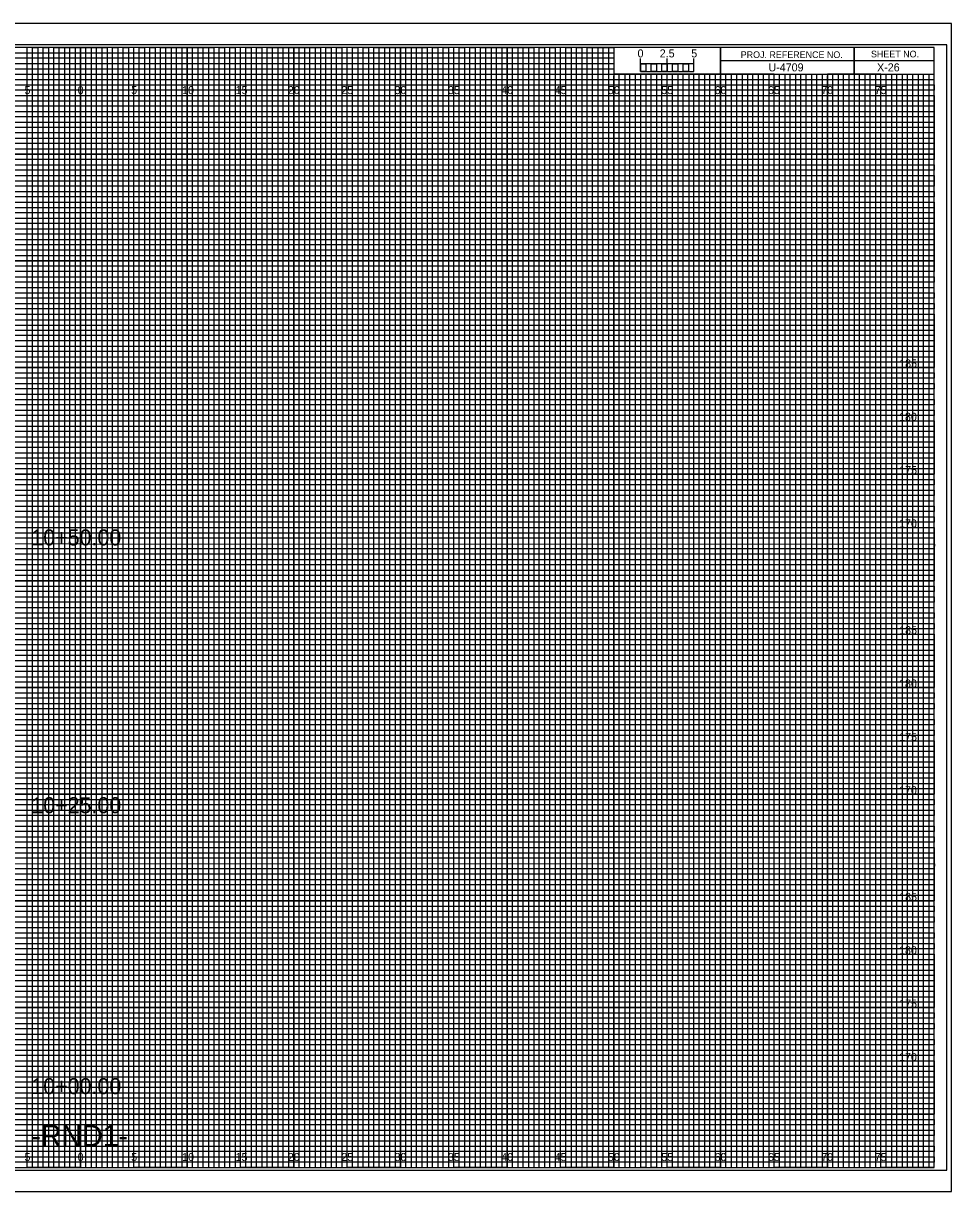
# Model space of a CAD drawing. Extents: x -7 to 162, y -2 to 107.
# Drawn here: x 74.6 to 161.7, y -2.3 to 107.3 of the extents above; entities that cross this region are included whole.
import ezdxf

# ---------------------------------------------------------------- set-up
doc = ezdxf.new("R2010")
doc.units = 0
for name, color, linetype in [('Prop XS Alignment Label', 7, 'Continuous'), ('Prop XS Bar Scale Labels', 7, 'Continuous'), ('Prop XS Elevation Labels', 7, 'Continuous'), ('Prop XS Offset Labels', 7, 'Continuous'), ('Prop XS Project Number', 7, 'Continuous'), ('Prop XS Sheet Number', 7, 'Continuous'), ('Prop XS Station Labels', 7, 'Continuous'), ('Sheet Cross Section CELL', 7, 'Continuous'), ('Sheet Cross Section Grid Major CELL', 7, 'Continuous'), ('Sheet Cross Section Grid Middle CELL', 7, 'Continuous'), ('Sheet Cross Section Grid Minor 1 CELL', 7, 'Continuous'), ('Sheet Cross Section Grid Minor 2 CELL', 7, 'Continuous'), ('Sheet Cross Section Scale CELL', 7, 'Continuous'), ('Sheet Cutting Line CELL', 7, 'Continuous'), ('Sheet DOT Grid CELL', 7, 'Continuous'), ('Sheet Plot Border Inside CELL', 7, 'Continuous'), ('Sheet Plot Border Outside CELL', 7, 'Continuous')]:
    doc.layers.add(name, color=color, linetype=linetype)

msp = doc.modelspace()

# ---------------------------------------------------------------- linework, layer by layer
at = {"layer": 'Sheet Cross Section CELL'}
for p, q in [((152.5, 105), (152.5, 102.5)), ((152.5, 102.5), (152.5, 105)), ((160, 103.75), (140, 103.75)), ((140, 103.75), (140, 102.5)), ((140, 102.5), (160, 102.5))]:
    msp.add_line(p, q, dxfattribs=at)
for points in [[(160, 105), (0, 105), (0, 0), (160, 0)], [(140, 105), (130, 105), (130, 102.52), (140, 102.52)], [(160, 105), (140, 105), (140, 102.5), (160, 102.5)]]:
    msp.add_lwpolyline(points, close=True, dxfattribs=at)
at = {"layer": 'Sheet Cross Section Grid Major CELL'}
for p, q in [((75, 105), (70, 105)), ((75, 0), (75, 105)), ((85, 105), (80, 105)), ((80, 105), (80, 0)), ((85, 0), (85, 105)), ((95, 105), (90, 105)), ((90, 105), (90, 0)), ((95, 0), (95, 105)), ((105, 105), (100, 105)), ((100, 105), (100, 0)), ((105, 0), (105, 105)), ((115, 105), (110, 105)), ((110, 105), (110, 0)), ((115, 0), (115, 105)), ((125, 105), (120, 105)), ((120, 105), (120, 0)), ((125, 0), (125, 105)), ((130, 105), (130, 0)), ((135, 0), (135, 102.5)), ((145, 102.5), (140, 102.5)), ((140, 102.5), (140, 0)), ((145, 0), (145, 102.5)), ((155, 102.5), (150, 102.5)), ((150, 102.5), (150, 0)), ((155, 0), (155, 102.5)), ((80, 0), (75, 0)), ((90, 0), (85, 0)), ((100, 0), (95, 0)), ((110, 0), (105, 0)), ((120, 0), (115, 0)), ((130, 0), (125, 0)), ((140, 0), (135, 0)), ((150, 0), (145, 0)), ((160, 0), (155, 0)), ((160, 0), (160, 0))]:
    msp.add_line(p, q, dxfattribs=at)
for points in [[(0, 100), (160, 100), (160, 95), (0, 95)], [(0, 90), (160, 90), (160, 85), (0, 85)], [(0, 80), (160, 80), (160, 75), (0, 75)], [(0, 70), (160, 70), (160, 65), (0, 65)], [(0, 60), (160, 60), (160, 55), (0, 55)], [(0, 50), (160, 50), (160, 45), (0, 45)], [(0, 40), (160, 40), (160, 35), (0, 35)], [(0, 30), (160, 30), (160, 25), (0, 25)], [(0, 20), (160, 20), (160, 15), (0, 15)], [(0, 10), (160, 10), (160, 5), (0, 5)]]:
    msp.add_lwpolyline(points, dxfattribs=at)
at = {"layer": 'Sheet Cross Section Grid Middle CELL'}
for points in [[(72.5, 0), (77.5, 0), (77.5, 105), (82.5, 105), (82.5, 0), (87.5, 0), (87.5, 105), (92.5, 105), (92.5, 0), (97.5, 0), (97.5, 105), (102.5, 105), (102.5, 0), (107.5, 0), (107.5, 105), (112.5, 105), (112.5, 0), (117.5, 0), (117.5, 105), (122.5, 105), (122.5, 0), (127.5, 0), (127.5, 105), (129.97, 105), (130, 105), (130, 102.5), (132.5, 102.5), (132.5, 0), (137.5, 0), (137.5, 102.5), (142.5, 102.5), (142.5, 0), (147.5, 0), (147.5, 102.5), (152.5, 102.5), (152.5, 0), (157.5, 0), (157.5, 102.5)], [(0, 102.5), (137.5, 102.5)], [(0, 92.5), (160, 92.5), (160, 97.5), (0, 97.5)], [(0, 82.5), (160, 82.5), (160, 87.5), (0, 87.5)], [(0, 72.5), (160, 72.5), (160, 77.5), (0, 77.5)], [(0, 62.5), (160, 62.5), (160, 67.5), (0, 67.5)], [(0, 52.5), (160, 52.5), (160, 57.5), (0, 57.5)], [(0, 42.5), (160, 42.5), (160, 47.5), (0, 47.5)], [(0, 32.5), (160, 32.5), (160, 37.5), (0, 37.5)], [(0, 22.5), (160, 22.5), (160, 27.5), (0, 27.5)], [(0, 12.5), (160, 12.5), (160, 17.5), (0, 17.5)], [(0, 2.5), (160, 2.5), (160, 7.5), (0, 7.5)]]:
    msp.add_lwpolyline(points, dxfattribs=at)
at = {"layer": 'Sheet Cross Section Grid Minor 1 CELL'}
for p, q in [((0, 104.5), (130, 104.5)), ((130, 104.5), (130, 103.99)), ((130, 103.99), (0, 103.99)), ((0, 103.5), (130, 103.5)), ((130, 102.95), (0, 102.95)), ((130, 103.5), (130, 102.95)), ((0, 102), (160, 102))]:
    msp.add_line(p, q, dxfattribs=at)
for points in [[(0, 101.5), (135, 101.5), (160, 101.5), (160, 101), (0, 101)], [(0, 100.5), (160, 100.5), (160, 99.5), (0, 99.5)], [(0, 99), (160, 99), (160, 98.5), (0, 98.49)], [(0, 98), (160, 98), (160, 97), (0, 97)], [(0, 96.5), (160, 96.5), (160, 96), (0, 96)], [(0, 95.5), (160, 95.5), (160, 94.5), (0, 94.5)], [(0, 94), (160, 94), (160, 93.5), (0, 93.5)], [(0, 93), (160, 93), (160, 92), (0, 92)], [(0, 91.5), (160, 91.5), (160, 91), (0, 91)], [(0, 90.5), (160, 90.5), (160, 89.5), (0, 89.5)], [(0, 89), (160, 89), (160, 88.5), (0, 88.5)], [(0, 88), (160, 88), (160, 86.98), (160, 86.5), (160, 86), (0, 86)], [(0, 87), (160, 87), (160, 86.5), (0, 86.5)], [(0, 85.5), (160, 85.5), (160, 84.5), (0, 84.52)], [(0, 84.52), (160, 84.5), (160, 84), (0, 84)], [(0, 83.5), (160, 83.5), (160, 83), (0, 83)], [(0, 82), (160, 82), (160, 81.5), (0, 81.5)], [(0, 81), (160, 81), (160, 80.5), (0, 80.5)], [(-0.04, 79.45), (160, 79.45), (160, 78.94), (-0.04, 78.94)], [(0, 78.5), (160, 78.5), (160, 78), (0, 78)], [(0, 77), (160, 77), (160, 76.5), (0, 76.5)], [(0, 76), (160, 76), (160, 75.5), (0, 75.5)], [(0, 74.5), (160, 74.5), (160, 74), (0, 74)], [(0, 73.5), (160, 73.5), (160, 73), (0, 73)], [(0, 72), (160, 72), (160, 71.5), (0, 71.5)], [(0, 71), (160, 71), (160, 70.5), (0, 70.5)], [(0, 69.5), (160, 69.5), (160, 68.99), (0, 69)], [(0, 68.5), (160, 68.5), (160, 68), (0, 68)], [(0, 67), (160, 67), (160, 66.5), (0, 66.5)], [(0, 66), (160, 66), (160, 65.5), (0, 65.5)], [(0, 64.5), (160, 64.5), (160, 64), (0, 64)], [(0, 63.5), (160, 63.5), (160, 63), (0, 63)], [(0, 62), (160, 62), (160, 61.5), (0, 61.5)], [(0, 61), (160, 61), (160, 60.5), (0, 60.5)], [(0, 59.5), (160, 59.5), (160, 59), (0, 59)], [(0, 58.5), (160.03, 58.45), (160, 58), (0, 58)], [(0, 57), (160, 57), (160, 56.5), (0, 56.5)], [(0, 56), (160, 56), (160, 55.5), (0, 55.5)], [(0, 54.5), (160, 54.5), (160, 54), (0, 54)], [(0, 53.5), (160, 53.5), (160, 53), (0, 53)], [(0, 52), (160, 52), (160, 51.5), (0, 51.5)], [(0, 51), (160, 51), (160, 50.5), (0, 50.5)], [(0, 49.5), (160, 49.5), (160, 49), (0, 49)], [(0, 48.5), (160, 48.5), (160, 48), (0, 48)], [(0, 47), (160, 47), (160, 46.5), (0, 46.5)], [(0, 46), (160, 46), (160, 45.5), (0, 45.5)], [(0, 44.5), (160, 44.5), (160, 44), (0, 44)], [(0, 43.5), (160, 43.5), (160, 43), (0, 43)], [(0, 42), (160, 42), (160, 41.5), (0, 41.5)], [(0, 41), (160, 41), (160, 40.5), (0, 40.5)], [(0, 39.5), (160, 39.5), (160, 38.99), (0, 39)], [(0, 38.5), (160, 38.5), (160, 38), (0, 38)], [(0, 37), (160, 37), (160, 36.5), (0, 36.5)], [(0, 36), (160, 36), (160, 35.5), (0, 35.5)], [(0, 34.5), (160, 34.5), (160, 34), (0, 34)], [(0, 33.5), (160, 33.5), (160, 33), (0, 33)], [(0, 32), (160, 32), (160, 31.5), (0, 31.5)], [(0, 31), (160, 31), (160, 30.5), (0, 30.5)], [(0, 29.5), (160, 29.5), (160, 29), (0, 29)], [(0, 28.5), (160.03, 28.46), (160, 28), (0, 28)], [(0, 27), (160, 27), (160, 26.5), (0, 26.5)], [(0, 26), (160, 26), (160, 25.5), (0, 25.5)], [(0, 24.5), (160, 24.5), (160, 24), (0, 24)], [(0, 23.5), (160, 23.5), (160, 23), (0, 23)], [(0, 22), (160, 22), (160, 21.5), (0, 21.5)], [(0, 21), (160, 21), (160, 20.5), (0, 20.5)], [(0, 19.5), (160, 19.5), (160, 19), (0, 19)], [(0, 18.5), (160, 18.5), (160, 18), (0, 18)], [(0, 17), (160, 17), (160, 16.5), (0, 16.5)], [(0, 16), (160, 16), (160, 15.5), (0, 15.5)], [(0, 14.5), (160, 14.5), (160, 14), (0, 14)], [(0, 13.5), (160, 13.5), (160, 13), (0, 13)], [(0, 12), (160, 12), (160, 11.5), (0, 11.5)], [(0, 11), (160, 11), (160, 10.5), (0, 10.5)], [(0, 9.5), (160, 9.5), (160, 9), (0, 9)], [(0, 8.5), (160, 8.5), (160, 8), (0, 8)], [(0, 7), (160, 7), (160, 6.5), (0, 6.5)], [(0, 6), (160, 6), (160, 5.5), (0, 5.5)], [(0, 4.5), (160, 4.5), (160, 4), (0, 4)], [(0, 3.5), (160, 3.5), (160, 3), (0, 3)], [(0, 2), (160, 2), (160, 1.5), (0, 1.5)], [(0, 1), (160, 1), (160, 0.5), (0, 0.5)]]:
    msp.add_lwpolyline(points, dxfattribs=at)
at = {"layer": 'Sheet Cross Section Grid Minor 2 CELL'}
for p, q in [((133.5, 102.5), (133, 102.5)), ((133, 102.5), (133, 0)), ((133.5, 0), (133.5, 102.5)), ((134.5, 102.5), (134, 102.5)), ((134, 102.5), (134, 0)), ((134.5, 0), (134.5, 102.5)), ((133, 0), (132.5, 0)), ((134, 0), (133.5, 0))]:
    msp.add_line(p, q, dxfattribs=at)
for points in [[(75, 0), (75.5, 0), (75.5, 105), (76, 105), (76, 0)], [(76, 0), (76.5, 0), (76.5, 105), (77, 105), (77, 0)], [(77.5, 0), (78, 0), (78, 105), (78.5, 105), (78.5, 0)], [(78.5, 0), (79, 0), (79, 105), (79.5, 105), (79.5, 0)], [(80, 0), (80.5, 0), (80.5, 105), (81, 105), (81, 0)], [(81, 0), (81.5, 0), (81.5, 105), (82, 105), (82, 0)], [(82.5, 0), (83, 0), (83, 105), (83.5, 105), (83.5, 0)], [(83.5, 0), (84, 0), (84, 105), (84.5, 105), (84.5, 0)], [(85, 0), (85.5, 0), (85.5, 105), (86, 105), (86, 0)], [(86, 0), (86.5, 0), (86.5, 105), (87, 105), (87, 0)], [(87.5, 0), (88, 0), (88, 105), (88.5, 105), (88.5, 0)], [(88.5, 0), (89, 0), (89, 105), (89.5, 105), (89.5, 0)], [(90, 0), (90.5, 0), (90.5, 105), (91, 105), (91, 0)], [(91, 0), (91.5, 0), (91.5, 105), (92, 105), (92, 0)], [(92.5, 0), (93, 0), (93, 105), (93.5, 105), (93.5, 0)], [(93.5, 0), (94, 0), (94, 105), (94.5, 105), (94.5, 0)], [(95, 0), (95.5, 0), (95.5, 105), (96, 105), (96, 0)], [(96, 0), (96.5, 0), (96.5, 105), (97, 105), (97, 0)], [(97.5, 0), (98, 0), (98, 105), (98.5, 105), (98.5, 0)], [(98.5, 0), (99, 0), (99, 105), (99.5, 105), (99.5, 0)], [(100, 0), (100.5, 0), (100.5, 105), (101, 105), (101, 0)], [(101, 0), (101.5, 0), (101.5, 105), (102, 105), (102, 0)], [(102.5, 0), (103, 0), (103, 105), (103.5, 105), (103.5, 0)], [(103.5, 0), (104, 0), (104, 105), (104.5, 105), (104.5, 0)], [(105, 0), (105.5, 0), (105.5, 105), (106, 105), (106, 0)], [(106, 0), (106.5, 0), (106.5, 105), (107, 105), (107, 0)], [(107.5, 0), (108, 0), (108, 105), (108.5, 105), (108.5, 0)], [(108.5, 0), (109, 0), (109, 105), (109.5, 105), (109.5, 0)], [(110, 0), (110.5, 0), (110.5, 105), (111, 105), (111, 0)], [(111, 0), (111.5, 0), (111.5, 105), (112, 105), (112, 0)], [(112.5, 0), (113, 0), (113, 105), (113.5, 105), (113.5, 0)], [(113.5, 0), (114, 0), (114, 105), (114.5, 105), (114.5, 0)], [(115, 0), (115.5, 0), (115.5, 105), (116, 105), (116, 0)], [(116, 0), (116.5, 0), (116.5, 105), (117, 105), (117, 0)], [(117.5, 0), (118, 0), (118, 105), (118.5, 105), (118.5, 0)], [(118.5, 0), (119, 0), (119, 105), (119.5, 105), (119.5, 0)], [(120, 0), (120.5, 0), (120.5, 105), (121, 105), (121, 0)], [(121, 0), (121.5, 0), (121.5, 105), (122, 105), (122, 0)], [(122.5, 0), (123, 0), (123, 105), (123.5, 105), (123.5, 0)], [(123.5, 0), (124, 0), (124, 105), (124.5, 105), (124.5, 0)], [(125, 0), (125.5, 0), (125.5, 105), (126, 105), (126, 0)], [(126, 0), (126.5, 0), (126.5, 105), (127, 105), (127, 0)], [(127.5, 0), (128, 0), (128, 105), (128.5, 105), (128.5, 0)], [(128.5, 0), (129, 0), (129, 105), (129.5, 105), (129.5, 0)], [(130, 0), (130.5, 0), (130.5, 102.5), (131.01, 102.5), (131.01, 0)], [(131, 0), (131.5, 0), (131.5, 102.5), (132, 102.5), (132, 0)], [(135, 0), (135.49, 0), (135.49, 102.5), (136, 102.5), (136, 0)], [(136, 0), (136.5, 0), (136.5, 102.5), (137.03, 102.5), (137.03, 0)], [(137.5, 0), (138, 0), (138, 102.5), (138.5, 102.5), (138.5, 0)], [(138.5, 0), (139, 0), (139, 102.5), (139.5, 102.5), (139.5, 0)], [(140, 0), (140.5, 0), (140.5, 102.5), (141, 102.5), (141, 0)], [(141, 0), (141.5, 0), (141.5, 102.5), (142, 102.5), (142, 0)], [(142.5, 0), (143, 0), (143, 102.5), (143.5, 102.5), (143.5, 0)], [(143.5, 0), (144, 0), (144, 102.5), (144.5, 102.5), (144.5, 0)], [(145, 0), (145.5, 0), (145.5, 102.5), (146, 102.5), (146, 0)], [(146, 0), (146.5, 0), (146.5, 102.5), (147, 102.5), (147, 0)], [(147.5, 0), (148, 0), (148, 102.5), (148.5, 102.5), (148.5, 0)], [(148.5, 0), (149, 0), (149, 102.5), (149.5, 102.5), (149.5, 0)], [(150, 0), (150.5, 0), (150.5, 102.5), (151, 102.5), (151, 0)], [(151, 0), (151.5, 0), (151.5, 102.5), (152, 102.5), (152, 0)], [(152.5, 0), (153, 0), (153, 102.5), (153.5, 102.5), (153.5, 0)], [(153.5, 0), (154, 0), (154, 102.5), (154.5, 102.5), (154.5, 0)], [(155, 0), (155.5, 0), (155.5, 102.5), (156, 102.5), (156, 0)], [(156, 0), (156.5, 0), (156.5, 102.5), (157, 102.5), (157, 0)], [(157.5, 0), (158, 0), (158, 102.5), (158.5, 102.5), (158.5, 0)], [(158.5, 0), (159, 0), (159, 102.5), (159.5, 102.5), (159.5, 0)]]:
    msp.add_lwpolyline(points, dxfattribs=at)
at = {"layer": 'Sheet Cross Section Scale CELL'}
for p, q in [((132.5, 102.75), (132.5, 103.95)), ((132.5, 103.45), (132.5, 103.95)), ((135, 102.75), (135, 103.95)), ((137.5, 102.75), (137.5, 103.95)), ((137.5, 103.45), (137.5, 103.95))]:
    msp.add_line(p, q, dxfattribs=at)
for points in [[(137.5, 103.45), (132.5, 103.45), (132.5, 102.75), (137.5, 102.75)], [(132.5, 103.45), (133, 103.45), (133, 102.75), (132.5, 102.75)], [(133.5, 103.45), (134, 103.45), (134, 102.75), (133.5, 102.75)], [(134.5, 103.45), (135, 103.45), (135, 102.75), (134.5, 102.75)], [(135.5, 103.45), (136, 103.45), (136, 102.75), (135.5, 102.75)], [(136.5, 103.45), (137, 103.45), (137, 102.75), (136.5, 102.75)]]:
    msp.add_lwpolyline(points, close=True, dxfattribs=at)
at = {"layer": 'Sheet Cutting Line CELL'}
for p, q in [((161.65, 107.25), (-6.7, 107.25)), ((-6.7, -2.25), (161.65, -2.25))]:
    msp.add_line(p, q, dxfattribs=at)
at = {"layer": 'Sheet DOT Grid CELL'}
for p, q in [((75, 0), (75, 105)), ((80, 0), (80, 105)), ((85, 0), (85, 105)), ((90, 0), (90, 105)), ((95, 0), (95, 105)), ((100, 0), (100, 105)), ((105, 0), (105, 105)), ((110, 0), (110, 105)), ((115, 0), (115, 105)), ((120, 0), (120, 105)), ((125, 0), (125, 105)), ((130, 0), (130, 102.34)), ((135, 0), (135, 102.34)), ((140, 0), (140, 102.34)), ((145, 0), (145, 102.34)), ((150, 0), (150, 102.34)), ((155, 0), (155, 102.34)), ((0, 100), (160, 100)), ((0, 95), (160, 95)), ((0, 90), (160, 90)), ((0, 85), (160, 85)), ((0, 80), (160, 80)), ((0, 75), (160, 75)), ((0, 70), (160, 70)), ((0, 65), (160, 65)), ((0, 60), (160, 60)), ((0, 55), (160, 55)), ((0, 50), (160, 50)), ((0, 45), (160, 45)), ((0, 40), (160, 40)), ((0, 35), (160, 35)), ((0, 30), (160, 30)), ((0, 25), (160, 25)), ((0, 20), (160, 20)), ((0, 15), (160, 15)), ((0, 10), (160, 10)), ((0, 5), (160, 5))]:
    msp.add_line(p, q, dxfattribs=at)
at = {"layer": 'Sheet Plot Border Inside CELL'}
msp.add_lwpolyline([(-5.4, -0.25), (161.2, -0.25), (161.2, 105.25), (-5.4, 105.25)], close=True, dxfattribs=at)
at = {"layer": 'Sheet Plot Border Outside CELL'}
msp.add_lwpolyline([(-6.7, -2.25), (161.65, -2.25), (161.65, 107.25), (-6.7, 107.25)], close=True, dxfattribs=at)

# ---------------------------------------------------------------- texts
at = {"layer": 'Prop XS Alignment Label'}
msp.add_text('-RND1-', height=2, dxfattribs=at).set_placement((75.39, 2))
at = {"layer": 'Prop XS Bar Scale Labels'}
for s, p in [('2.5', (134.29, 104.06)), ('5', (137.24, 104.06))]:
    msp.add_text(s, height=0.75, dxfattribs=at).set_placement(p)
at = {"layer": 'Prop XS Elevation Labels'}
for s, p in [('185', (156.73, 75)), ('180', (156.72, 70)), ('175', (156.73, 65)), ('170', (156.72, 60)), ('185', (156.73, 50)), ('180', (156.72, 45)), ('175', (156.73, 40)), ('170', (156.72, 35)), ('185', (156.73, 25)), ('180', (156.72, 20)), ('175', (156.73, 15)), ('170', (156.72, 10))]:
    msp.add_text(s, height=0.75, dxfattribs=at).set_placement(p)
at = {"layer": 'Prop XS Offset Labels'}
for s, p in [('5', (74.74, 100.62)), ('0', (79.73, 100.62)), ('0', (79.73, 100.62)), ('5', (84.74, 100.62)), ('10', (89.52, 100.62)), ('15', (94.53, 100.62)), ('20', (99.43, 100.62)), ('25', (104.44, 100.62)), ('30', (109.43, 100.62)), ('35', (114.44, 100.62)), ('40', (119.43, 100.62)), ('45', (124.44, 100.62)), ('50', (129.43, 100.62)), ('55', (134.44, 100.62)), ('60', (139.43, 100.62)), ('65', (144.44, 100.62)), ('70', (149.43, 100.62)), ('75', (154.44, 100.62)), ('5', (74.74, 0.62)), ('0', (79.73, 0.62)), ('0', (79.73, 0.62)), ('5', (84.74, 0.62)), ('10', (89.52, 0.62)), ('15', (94.53, 0.62)), ('20', (99.43, 0.62)), ('25', (104.44, 0.62)), ('30', (109.43, 0.62)), ('35', (114.44, 0.62)), ('40', (119.43, 0.62)), ('45', (124.44, 0.62)), ('50', (129.43, 0.62)), ('55', (134.44, 0.62)), ('60', (139.43, 0.62)), ('65', (144.44, 0.62)), ('70', (149.43, 0.62)), ('75', (154.44, 0.62))]:
    msp.add_text(s, height=0.75, dxfattribs=at).set_placement(p)
at = {"layer": 'Prop XS Project Number'}
msp.add_text('U-4709', height=0.75, dxfattribs=at).set_placement((144.48, 102.75))
at = {"layer": 'Prop XS Sheet Number'}
msp.add_text('X-26', height=0.75, dxfattribs=at).set_placement((154.66, 102.75))
at = {"layer": 'Prop XS Station Labels'}
for s, p in [('10+50.00', (75.39, 58.32)), ('10+25.00', (75.39, 33.22)), ('10+00.00', (75.39, 6.89))]:
    msp.add_text(s, height=1.5, dxfattribs=at).set_placement(p)
at = {"layer": 'Sheet Cross Section CELL'}
for s, p in [('PROJ. REFERENCE NO.', (141.88, 104)), ('SHEET NO.', (154.09, 104.06))]:
    msp.add_text(s, height=0.625, dxfattribs=at).set_placement(p)
at = {"layer": 'Sheet Cross Section Scale CELL'}
msp.add_text('0', height=0.75, dxfattribs=at).set_placement((132.21, 104.06))

doc.saveas('drawing.dxf')
